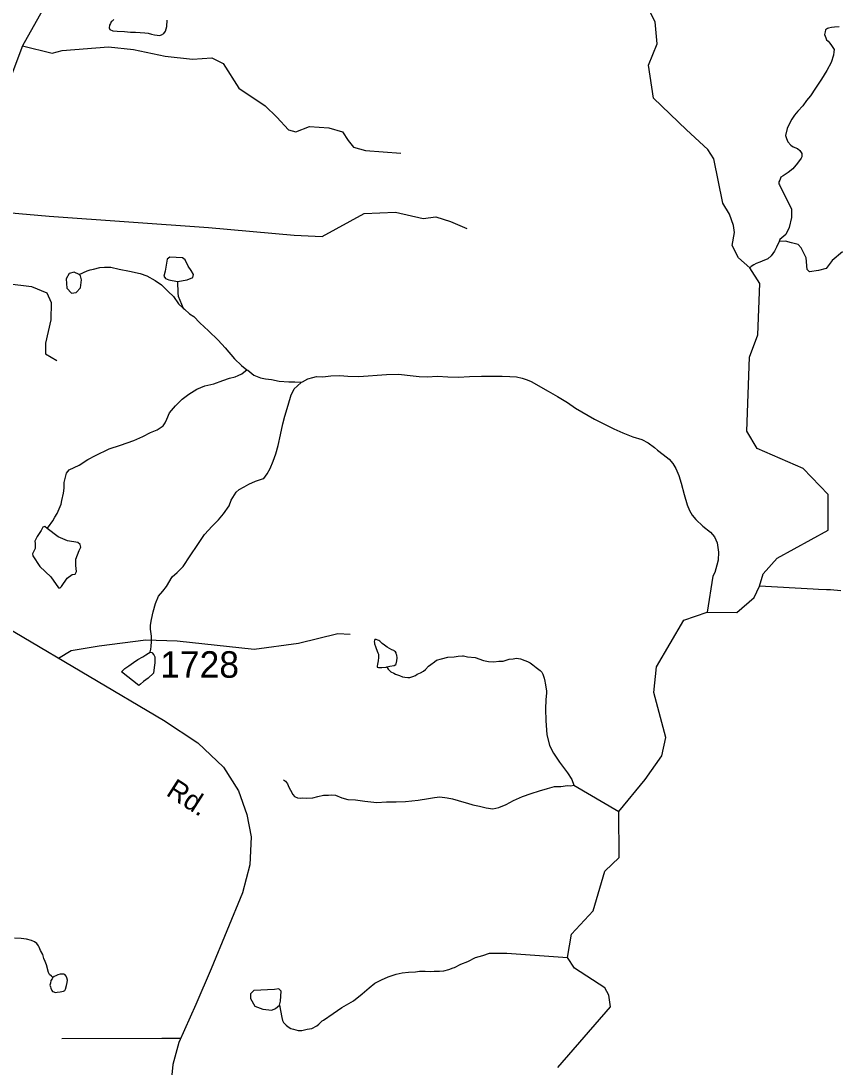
# Model space of a CAD drawing. Extents: x 2056842 to 2160602, y 826753 to 1016856.
# Drawn here: x 2083484 to 2087342, y 850234 to 855171 of the extents above; entities that cross this region are included whole.
import ezdxf

# ---------------------------------------------------------------- set-up
doc = ezdxf.new("R2010")
doc.units = 0
for name, color, linetype in [('Exist Hydrographic Creek Single Shore', 7, 'Continuous'), ('Exist Hydrographic Misc Water Feature', 7, 'Continuous'), ('Exist Road Non-System Type 51', 7, 'Continuous'), ('Exist Road Secondary Type 51 Attributed', 7, 'Continuous'), ('Exist Road Secondary Type 51 Label', 7, 'Continuous'), ('Exist Road Secondary Type 51 Number Label', 7, 'Continuous')]:
    doc.layers.add(name, color=color, linetype=linetype)

msp = doc.modelspace()

# ---------------------------------------------------------------- linework, layer by layer
at = {"layer": 'Exist Hydrographic Creek Single Shore'}
for points in [[(2086967.5, 853931.6), (2086921.5, 854006.2), (2086867.4, 854052.9), (2086838.4, 854110.9), (2086848.9, 854171.6), (2086843.7, 854205.8), (2086825.2, 854258.6), (2086793.6, 854311.3), (2086751.5, 854519.6), (2086722.5, 854564.4), (2086622.3, 854656.7), (2086466.3, 854806.4), (2086442.6, 854962), (2086484.8, 855062.2), (2086475.1, 855167), (2086370.6, 855369.8)], [(2087342, 855143.5), (2087319.9, 855141.2), (2087305.5, 855139.3), (2087291.6, 855137.3), (2087287.9, 855135.1), (2087278.1, 855129.3), (2087275.8, 855119), (2087274, 855107.2), (2087279.7, 855091.3), (2087282.4, 855081.1), (2087290.2, 855075.1), (2087298.4, 855065.3), (2087305.9, 855055.2), (2087318.5, 855035.5), (2087318, 855025.4), (2087316.2, 855009.5), (2087304.1, 854975.2), (2087284.2, 854937.2), (2087258.6, 854895.3), (2087230.7, 854853.2), (2087206.9, 854817.1), (2087188.7, 854795.1), (2087171.2, 854770.9), (2087146.8, 854745), (2087131, 854726.7), (2087119.1, 854706.6), (2087107.5, 854686.9), (2087097.4, 854662.8), (2087089.6, 854630.7), (2087093.7, 854616.7), (2087099.9, 854600.8), (2087113.8, 854584.9), (2087125.5, 854576.6), (2087145.6, 854568.7), (2087157.5, 854558.8), (2087165.9, 854544.9), (2087165.7, 854528.7), (2087163.8, 854522.9), (2087145.8, 854498.9), (2087124.1, 854472.9)], [(2087059.1, 854130.6), (2087047.2, 854102.8), (2087037.3, 854084.4), (2087021.3, 854062.5), (2087005.3, 854048.7), (2086979.1, 854036.4), (2086969, 854032.3), (2086951.6, 854026.4), (2086939.5, 854020.1), (2086927.4, 854012.2), (2086921.5, 854006.2)], [(2087357.5, 854081.9), (2087310.1, 854039.7), (2087281.1, 854002.8), (2087244.2, 853992.3), (2087202, 853987), (2087191.5, 853997.5), (2087186.2, 854052.9), (2087162.5, 854100.4), (2087149.3, 854116.2), (2087117.7, 854124.1), (2087088.7, 854132), (2087059.1, 854130.6)], [(2086967.3, 852502.5), (2086983.3, 852561.2), (2087050.3, 852635.3), (2087291.2, 852768.1), (2087290.2, 852935.5), (2087173.1, 853059.3), (2086956.2, 853152.3), (2086906.2, 853235.4), (2086920.1, 853583.6), (2086959.6, 853689.1), (2086967.5, 853931.6)], [(2084807.4, 853465.7), (2084811.5, 853467.9), (2084837.1, 853481.8), (2084859.5, 853487.8), (2084877.1, 853492), (2084907.2, 853491.9), (2084945.4, 853495.9), (2084987.4, 853498), (2085024.9, 853494.3), (2085077.4, 853492.5), (2085207.4, 853502.8), (2085265.3, 853503), (2085305.5, 853499.3), (2085361.4, 853493.3), (2085399.4, 853491.6), (2085447.4, 853493.6), (2085497.2, 853491.8), (2085547.4, 853489.8), (2085599.1, 853492.1), (2085655.3, 853494.6), (2085703.3, 853494.6), (2085753.5, 853494.7), (2085789.2, 853493), (2085821.2, 853490.9), (2085847.4, 853484.9), (2085871.2, 853476.9), (2085889.4, 853469.2), (2085969.4, 853423.4), (2086013.5, 853397.7), (2086061.5, 853369.7), (2086099.6, 853343.6), (2086188, 853292.1), (2086252, 853260.1), (2086279.9, 853246.5), (2086321.9, 853226.3), (2086369.9, 853208.5), (2086411.9, 853194.9), (2086441.9, 853179), (2086471.8, 853157), (2086485.9, 853145.1), (2086512, 853125.3), (2086540.3, 853103.2), (2086558.3, 853081.4), (2086572.5, 853059.3), (2086586.2, 853025.2), (2086596.5, 852989.5), (2086610.8, 852935.5), (2086625, 852887.4), (2086636.9, 852859.7), (2086649, 852837.6), (2086666.8, 852817.4), (2086699.4, 852785.7), (2086735.1, 852757.9), (2086755.2, 852735.8), (2086767.7, 852708), (2086773.4, 852664.1), (2086771.8, 852625.8), (2086765.6, 852602), (2086755.8, 852567.8), (2086745.9, 852549.8), (2086720.1, 852380.3)], [(2086016.2, 850231.8), (2086263.5, 850517.9), (2086255.6, 850573.2), (2086237.1, 850607.5), (2086094.8, 850699.8), (2086060.6, 850749.9), (2086079.8, 850860.9), (2086182.6, 850971.6), (2086237.9, 851158.8), (2086304.3, 851223.3), (2086303.3, 851439.9), (2086428.2, 851591.5), (2086506.7, 851702.2), (2086525.1, 851789.2), (2086468.2, 852000.9), (2086480.3, 852123.2), (2086609.4, 852342.1), (2086720.1, 852380.3), (2086859.7, 852379), (2086942.2, 852450.5), (2086967.3, 852502.5)], [(2087350, 852481.8), (2087302.3, 852485.8), (2087282.2, 852485.5), (2087244.2, 852487.3), (2087219.8, 852489.3), (2086967.3, 852502.5)], [(2084721.3, 851589.6), (2084731.3, 851583.6), (2084741.4, 851569.9), (2084747.3, 851554), (2084755.1, 851539.8), (2084765.4, 851519.9), (2084773.6, 851509.8), (2084787.3, 851504), (2084803.7, 851502), (2084813.7, 851504.1), (2084829.5, 851502.1), (2084859.7, 851504), (2084883.7, 851510.1), (2084909.7, 851516.4), (2084933.5, 851516.4), (2084949.5, 851518.4), (2084967.5, 851516.5), (2084997.5, 851504.7), (2085025.4, 851496.8), (2085061.7, 851494.9), (2085105.7, 851488.7), (2085161.7, 851483), (2085207.4, 851485), (2085253.4, 851485.3), (2085297.7, 851487.6), (2085357.5, 851493.5), (2085405.3, 851501.7), (2085433.2, 851505.9), (2085459, 851508.2), (2085493.3, 851504.2), (2085519.3, 851500.2), (2085545.2, 851492.2), (2085571.6, 851484.2), (2085589.3, 851478.3), (2085615.5, 851470.6), (2085645.6, 851464.4), (2085677.4, 851456.8), (2085709.4, 851452.7), (2085737.7, 851459), (2085771.5, 851472.9), (2085807.2, 851491.1), (2085849.3, 851511.1), (2085889.4, 851525.3), (2085929.2, 851537.5), (2085967.2, 851547.6), (2085999.4, 851557.7), (2086029.1, 851557.7), (2086061.3, 851561.7), (2086077.1, 851560.1), (2086091.6, 851563.6)], [(2086091.6, 851563.6), (2086303.3, 851439.9)], [(2084703, 850525.8), (2084714.7, 850467.8), (2084716.5, 850453.8), (2084722.5, 850443.9), (2084734.6, 850431.9), (2084744.6, 850423.9), (2084756.9, 850416), (2084768.6, 850411.8), (2084790.6, 850406), (2084808.8, 850406.1), (2084832.8, 850412.2), (2084854.8, 850416.1), (2084879, 850428.3), (2084888.8, 850436.2), (2084904.6, 850452.4), (2084910.9, 850454.3), (2084956.7, 850486.7), (2084996.7, 850514.8), (2085052.4, 850546.9), (2085092.2, 850579), (2085126.2, 850607.1), (2085152.1, 850629.1), (2085184.1, 850645), (2085216.1, 850659.2), (2085253.8, 850671.3), (2085282.1, 850677.6), (2085312, 850681.6), (2085343.8, 850683.7), (2085363.7, 850685.9), (2085390.1, 850686), (2085413.9, 850684), (2085431.8, 850686.1), (2085458.2, 850686.2), (2085478.1, 850688.1), (2085501.9, 850694.2), (2085521.6, 850702.1), (2085527.9, 850704), (2085557.9, 850718.6), (2085591.7, 850732.5), (2085627.8, 850750.6), (2085661.8, 850760.8), (2085693.6, 850771), (2085719.5, 850770.7), (2085751.4, 850770.8), (2085775.6, 850771.1), (2086060.6, 850749.9)]]:
    msp.add_lwpolyline(points, dxfattribs=at)
at = {"layer": 'Exist Hydrographic Misc Water Feature'}
for points in [[(2083921.1, 855178.3), (2083913.5, 855170.5), (2083909.4, 855166.3), (2083905.5, 855158.4), (2083901.6, 855150.4), (2083899.5, 855138.2), (2083903.2, 855130.3), (2083917.2, 855124.5), (2083937.3, 855122.3), (2083971.3, 855120.7), (2083999.6, 855118.5), (2084017.4, 855118.6), (2084023.4, 855118.6), (2084067.3, 855114.7), (2084083.5, 855112.7), (2084099.4, 855109), (2084113.2, 855104.9), (2084125.7, 855103), (2084137.6, 855102.8), (2084147.2, 855105), (2084157.7, 855111.2), (2084165.1, 855123), (2084171.4, 855145.2), (2084173.3, 855174.9)], [(2087124.1, 854472.9), (2087101.9, 854454.8), (2087078.3, 854440.5), (2087068.1, 854432.8), (2087062.3, 854418.6), (2087058, 854410.8), (2087058.4, 854402.6), (2087060.3, 854396.6), (2087117.7, 854282.3), (2087117.7, 854242.7), (2087107.2, 854195.3), (2087091.4, 854163.6), (2087062.8, 854138.6), (2087059.1, 854130.6)], [(2084221.2, 853941.8), (2084267.4, 853949.7), (2084293.7, 853960.2), (2084297.7, 853974.7), (2084285.8, 853993.2), (2084272.6, 854013), (2084258.1, 854043.3), (2084245, 854052.5), (2084185.7, 854055.2), (2084173.8, 854045.9), (2084163.3, 853989.2), (2084156.7, 853965.5), (2084164.6, 853955), (2084181.7, 853948.4), (2084221.2, 853941.8)], [(2083758.8, 853973.4), (2083733.8, 853985.3), (2083711.4, 853978.7), (2083696.9, 853953.6), (2083699.5, 853910.1), (2083721.9, 853886.4), (2083744.3, 853889.1), (2083764.1, 853911.5), (2083769.4, 853948.4), (2083764.1, 853968.1), (2083758.8, 853973.4)], [(2083758.8, 853973.4), (2083795.4, 853991.6), (2083810, 853996.7), (2083825.6, 853998.8), (2083855.9, 854006.8), (2083877.9, 854008.7), (2083907.6, 854009), (2083946, 853998.8), (2083995.8, 853989.2), (2084045.8, 853979.1), (2084078, 853967.4), (2084116, 853945.4), (2084146.1, 853925.4), (2084178.3, 853893.8), (2084202.3, 853869.8), (2084226.5, 853835.7), (2084248.6, 853815.8)], [(2084221.2, 853941.8), (2084224.2, 853886), (2084224.4, 853871.8), (2084248.6, 853815.8)], [(2084248.6, 853815.8), (2084254.4, 853810), (2084278.4, 853788.1), (2084298.4, 853776.1), (2084326.7, 853746.3), (2084368.8, 853708.3), (2084412.9, 853664.6), (2084446.9, 853628.6), (2084491, 853576.6), (2084523, 853544.9), (2084549, 853524.7)], [(2083607.6, 852776), (2083614, 852783.9), (2083633.5, 852812.2), (2083643.5, 852828.2), (2083653.6, 852846.1), (2083663.2, 852868.2), (2083673.2, 852890.2), (2083677.1, 852908.3), (2083684.9, 852942.4), (2083687.2, 852966.4), (2083687, 852992.4), (2083698.9, 853036.5), (2083711, 853052.4), (2083758.8, 853074.4), (2083798.7, 853100.4), (2083834.4, 853120.6), (2083900.2, 853150.8), (2083952.7, 853169.2), (2084016.3, 853191.2), (2084058.3, 853209.2), (2084094.2, 853227.7), (2084126.2, 853241.5), (2084154.3, 853259.6), (2084164.3, 853273.9), (2084171.9, 853291.7), (2084184, 853321.6), (2084212.1, 853353.9), (2084243.7, 853386), (2084275.7, 853409.9), (2084313.4, 853432.2), (2084351.4, 853448.4), (2084393.4, 853458.2), (2084435.2, 853474.6), (2084467.6, 853484.7), (2084493.2, 853490.6), (2084507.4, 853497), (2084525.2, 853504.8), (2084535.1, 853513), (2084549, 853524.7)], [(2084549, 853524.7), (2084552.9, 853522.9), (2084581.2, 853499.2), (2084613.2, 853487), (2084637.4, 853481.3), (2084665.1, 853479.1), (2084701.2, 853471.2), (2084747.3, 853467.5), (2084775.4, 853467.7), (2084807.4, 853465.7)], [(2084093.2, 852191.5), (2084095.7, 852205.8), (2084097.1, 852217.7), (2084099.5, 852241.7), (2084099.1, 852267.7), (2084095, 852299.6), (2084095, 852319.5), (2084098.9, 852345.7), (2084107.1, 852381.8), (2084118.8, 852421.8), (2084132.6, 852455.8), (2084152.7, 852479.9), (2084170.5, 852502), (2084196.3, 852548), (2084220.5, 852567.9), (2084248.2, 852596.1), (2084282, 852646.2), (2084317.7, 852700.4), (2084349.7, 852746.3), (2084385.6, 852786.3), (2084415.3, 852816.6), (2084439.1, 852844.7), (2084465, 852882.6), (2084475.2, 852908.6), (2084499, 852946.8), (2084512.9, 852958.9), (2084536.9, 852972.7), (2084558.9, 852984.8), (2084589, 852998.9), (2084622.8, 853009.2), (2084628.8, 853011.1), (2084644.8, 853033), (2084658.9, 853059.3), (2084672.7, 853093.4), (2084686.4, 853127.3), (2084696.5, 853167.2), (2084708.1, 853217.4), (2084718.2, 853269.4), (2084727.8, 853305.3), (2084743.8, 853357.6), (2084757.4, 853405.5), (2084763.5, 853417.5), (2084771.5, 853433.8), (2084785.7, 853447.5), (2084807.4, 853465.7)], [(2083607.6, 852776), (2083596.8, 852784.4), (2083586.2, 852781.7), (2083578.3, 852765.9), (2083559.9, 852736.9), (2083549.3, 852715.8), (2083550.6, 852703.9), (2083550.6, 852680.2), (2083537.5, 852656.5), (2083540.1, 852645.9), (2083573, 852595.8), (2083624.4, 852547.1), (2083661.3, 852495.7), (2083667.9, 852495.7), (2083674.5, 852500.9), (2083700.8, 852540.5), (2083725.9, 852557.6), (2083739, 852560.2), (2083745.6, 852572.1), (2083743, 852601.1), (2083743, 852630.1), (2083757.5, 852671), (2083765.4, 852686.8), (2083762.8, 852700), (2083752.2, 852709.2), (2083703.5, 852717.1), (2083658.7, 852735.6), (2083607.6, 852776)], [(2085209.7, 852122.9), (2085223.6, 852125.3), (2085243.3, 852129.2), (2085251.7, 852133.2), (2085253.2, 852137.4), (2085255.6, 852151.2), (2085257.5, 852165.2), (2085255.6, 852177.2), (2085253.2, 852183.3), (2085253.4, 852189.3), (2085249.3, 852193.2), (2085245.4, 852197), (2085241.5, 852199.2), (2085233.3, 852203.3), (2085221, 852209.2), (2085210.9, 852215.2), (2085197.4, 852225), (2085187.1, 852233.1), (2085176.9, 852243.1), (2085171.1, 852246.9), (2085166.8, 852249.1), (2085159.1, 852251.1), (2085153.1, 852250.8), (2085151.3, 852247), (2085149, 852240.9), (2085151.3, 852236.9), (2085151.1, 852230.8), (2085155, 852218.9), (2085159.3, 852208.9), (2085167, 852189), (2085169.5, 852183), (2085169.3, 852174.9), (2085169.3, 852167.2), (2085167.5, 852150.8), (2085165.2, 852134.9), (2085163.6, 852125), (2085163.4, 852121), (2085169.5, 852118.9), (2085185.5, 852118.8), (2085205.4, 852121.1), (2085209.7, 852122.9)], [(2084093.2, 852191.5), (2084101.4, 852189.5), (2084109.6, 852179.7), (2084115.5, 852169.9), (2084115.5, 852159.8), (2084115.5, 852141.9), (2084111.9, 852119.7), (2084109.3, 852092.3), (2084082.9, 852068.5), (2084061.8, 852053.5), (2084047.9, 852041.4), (2084039.7, 852033.7), (2083957.7, 852099.3), (2083973.9, 852115.1), (2083991.7, 852127.4), (2084013.8, 852143.5), (2084035.6, 852157.2), (2084057.7, 852169.3), (2084073.3, 852179.5), (2084085.4, 852187.4), (2084093.2, 852191.5)], [(2085209.7, 852122.9), (2085211.5, 852119), (2085215.6, 852111.1), (2085227.3, 852099.2), (2085241.7, 852093.3), (2085249.5, 852087.3), (2085259.5, 852085.3), (2085269.4, 852081.4), (2085283.7, 852075.2), (2085293.6, 852073.3), (2085307.7, 852071.5), (2085317.6, 852071.7), (2085331.7, 852077.6), (2085343.8, 852081.5), (2085351.6, 852087.6), (2085367.6, 852093.7), (2085381.5, 852101.7), (2085391.4, 852109.6), (2085405.5, 852125.7), (2085417.4, 852133.6), (2085433.6, 852145.8), (2085443.5, 852154), (2085467.2, 852159.8), (2085497.6, 852168.1), (2085527.3, 852170.1), (2085545.4, 852172.2), (2085565.3, 852174.1), (2085571.4, 852174.4), (2085589.3, 852170.1), (2085625.3, 852166.6), (2085665.3, 852152.4), (2085689.3, 852148.4), (2085713.3, 852146.8), (2085737.5, 852148.8), (2085757.4, 852149), (2085785.5, 852159), (2085805.4, 852160.8), (2085821.4, 852162.9), (2085839.4, 852160.9), (2085859.3, 852153.1), (2085873.2, 852147.3), (2085885.3, 852141.4), (2085897.2, 852131.5), (2085913.6, 852119.3), (2085931.7, 852105.2), (2085939.7, 852097.5), (2085945.2, 852087.3), (2085951.6, 852069.3), (2085953.6, 852055.6), (2085955.7, 852045.5), (2085961.6, 852009.3), (2085961.6, 851999.6), (2085959.6, 851967.4), (2085957.9, 851923.5), (2085958.3, 851867.4), (2085964.3, 851803.6), (2085976.4, 851751.5), (2085994.6, 851715.5), (2086023.1, 851671.8), (2086042.8, 851647.7), (2086060.7, 851622.2), (2086081.8, 851590.5), (2086091.6, 851563.6)], [(2083634.3, 850656.4), (2083628.1, 850662.2), (2083618.5, 850670.5), (2083614.2, 850680.1), (2083603.9, 850716.1), (2083598.2, 850732.4), (2083592, 850746.3), (2083586.1, 850764.3), (2083575.8, 850784.1), (2083569.9, 850800), (2083565.8, 850806.3), (2083557.8, 850816), (2083547.5, 850824.1), (2083533.8, 850830.2), (2083510, 850837.9), (2083484, 850839.8), (2083453.6, 850841.6)], [(2083634.3, 850656.4), (2083630.4, 850650.5), (2083624.4, 850642.4), (2083622.4, 850630.2), (2083620.3, 850620.3), (2083622.4, 850612.3), (2083624.4, 850606.3), (2083628.7, 850594.3), (2083632.4, 850590.5), (2083638.4, 850588.4), (2083644.3, 850586.2), (2083654.2, 850586.4), (2083668.5, 850588.3), (2083684.5, 850592.3), (2083690.5, 850594.7), (2083694.4, 850600.6), (2083698.3, 850618.7), (2083702.2, 850632.7), (2083702.6, 850644.4), (2083700.3, 850654.5), (2083696.2, 850662.4), (2083690.3, 850670.6), (2083686.4, 850672.4), (2083682.1, 850672.6), (2083668.5, 850672.3), (2083658.1, 850668.6), (2083648, 850664.4), (2083640.2, 850660.4), (2083634.3, 850656.4)], [(2084703, 850525.8), (2084708.3, 850544.2), (2084710.9, 850591.7), (2084700.4, 850602.2), (2084679.3, 850599.6), (2084581.8, 850594.3), (2084566, 850578.5), (2084566, 850557.4), (2084587.1, 850520.5), (2084624, 850507.3), (2084666.2, 850502.1), (2084684.6, 850510), (2084703, 850525.8)]]:
    msp.add_lwpolyline(points, dxfattribs=at)
at = {"layer": 'Exist Road Non-System Type 51'}
for points in [[(2083491.5, 855053.9), (2083630.7, 855019.1), (2083678.4, 855031.5), (2083896.5, 855048.2), (2084014.9, 855035.7), (2084164.5, 855004.5), (2084293.2, 854990), (2084384.6, 854996.2), (2084436.6, 854969.2), (2084511.3, 854852.8), (2084634.9, 854770.7), (2084691, 854716.6), (2084745, 854656.4), (2084780.3, 854648.1), (2084844.7, 854673), (2084936.1, 854666.8), (2085000.5, 854648.1), (2085027.5, 854606.5), (2085052.4, 854575.3), (2085108.5, 854558.7), (2085274.6, 854546.2)], [(2083221.3, 854283.4), (2083616.1, 854250), (2084368, 854196), (2084772, 854159.6), (2084904.9, 854153.4), (2085102.2, 854261.5), (2085249.7, 854267.7), (2085380.6, 854238.6), (2085440.8, 854246.9), (2085509.3, 854224.1), (2085586.2, 854190.8)], [(2083109.9, 853969.7), (2083533.1, 853917.5), (2083605.8, 853888.4), (2083626.5, 853842.7), (2083624.4, 853759.5), (2083599.5, 853649.4), (2083599.5, 853599.5), (2083653.5, 853568.3)], [(2083660.6, 852163.7), (2083720.1, 852200.2), (2083853, 852221), (2084073.2, 852250.1), (2084220.7, 852245.9), (2084584.1, 852206.4), (2084792.9, 852234.5), (2084977.7, 852280.2), (2085035.9, 852276.1)], [(2084237.3, 850369.1), (2084148, 850369.1), (2083676.5, 850367)]]:
    msp.add_lwpolyline(points, dxfattribs=at)
at = {"layer": 'Exist Road Secondary Type 51 Attributed'}
for points in [[(2087449.7, 857409.9), (2087040.5, 857169.9), (2086532.2, 856865.9), (2086157.3, 856642.3), (2085516.1, 856263.7), (2085113.7, 856080.3), (2084712.8, 855964.9), (2084408, 855887.5), (2084270.9, 855828.3), (2084122.4, 855729.6), (2083844.7, 855515), (2083712.8, 855397.5), (2083612.6, 855268.2), (2083491.1, 855053), (2083445.4, 854932.5), (2083298.4, 854500.7), (2083113.1, 853978.5), (2082911.1, 853374.3), (2082828.5, 853174.2), (2082757.9, 853058.9), (2082670.7, 852966.4), (2082612.5, 852919.6)], [(2082612.5, 852919.6), (2082763.6, 852794.4), (2082984.8, 852607.3), (2083202.4, 852438.5), (2083454.7, 852285.7), (2084155.2, 851870.6), (2084318.2, 851764.6), (2084438.1, 851649.7), (2084509.8, 851537.5), (2084548.2, 851426.3), (2084569.5, 851319.8), (2084563.3, 851187.8), (2084529, 851055.8), (2084380, 850696.8), (2084308.3, 850528.5), (2084228.9, 850350.2), (2084199.8, 850245.3), (2084187.4, 850116.4)]]:
    msp.add_lwpolyline(points, dxfattribs=at)

# ---------------------------------------------------------------- texts
at = {"layer": 'Exist Road Secondary Type 51 Label'}
msp.add_text('Rd.', height=95, rotation=327.4822, dxfattribs=at).set_placement((2084163.3, 851519.1))
at = {"layer": 'Exist Road Secondary Type 51 Number Label'}
msp.add_text('1728', height=125, dxfattribs=at).set_placement((2084140.1, 852071.2))

doc.saveas('drawing.dxf')
